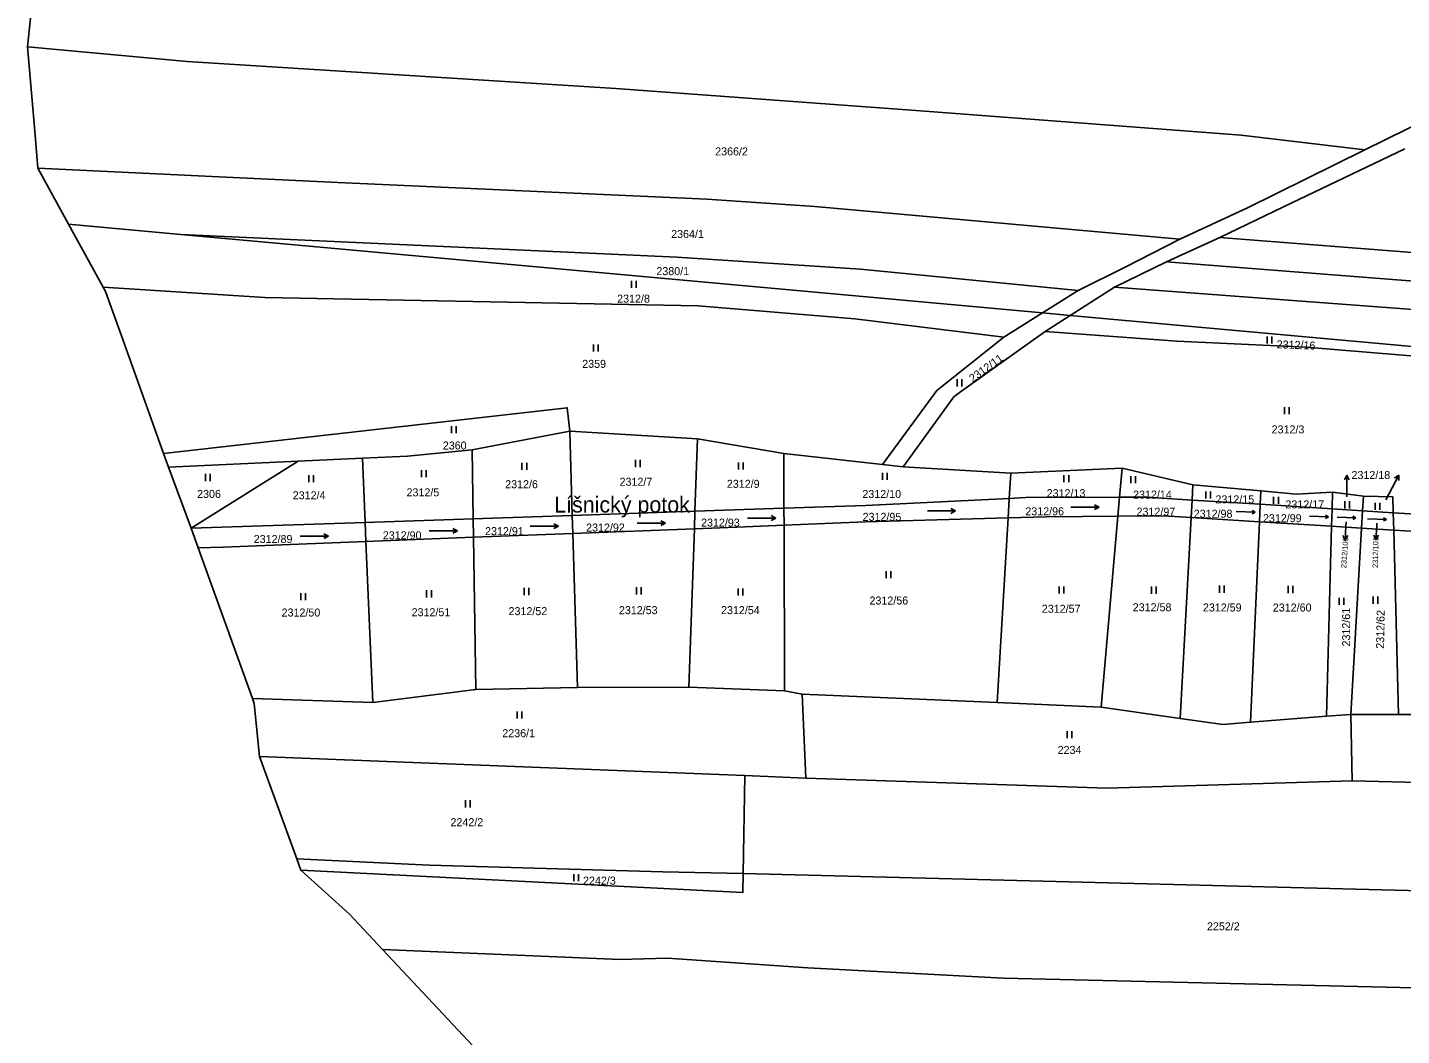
# Model space of a CAD drawing. Extents: x -776734 to -748832, y -1118122 to -976986.
# Drawn here: x -754505.9 to -754214.1, y -1116083.5 to -1115869.4 of the extents above; entities that cross this region are included whole.
import ezdxf

# ---------------------------------------------------------------- set-up
doc = ezdxf.new("R2010")
doc.units = 0
for name, color, linetype in [('KM_Hranice obce', 7, 'Continuous'), ('KM_Hranice parcel', 7, 'Continuous'), ('KM_Parcelní čísla', 7, 'Continuous'), ('KM_Pop  PČ popisy', 7, 'Continuous'), ('KM_Značky kultur', 7, 'Continuous')]:
    doc.layers.add(name, color=color, linetype=linetype)

msp = doc.modelspace()

# ---------------------------------------------------------------- linework, layer by layer
at = {"layer": 'KM_Hranice obce'}
for p, q in [((-754497.23, -1115911.22), (-754489.87, -1115924.53)), ((-754485.69, -1115935.7), (-754479.31, -1115953.55)), ((-754479.31, -1115953.55), (-754477.03, -1115959.92)), ((-754477.03, -1115959.92), (-754475.96, -1115962.78)), ((-754475.96, -1115962.78), (-754471.18, -1115975.77)), ((-754471.18, -1115975.77), (-754469.69, -1115979.94)), ((-754469.69, -1115979.94), (-754458.16, -1116011.92)), ((-754448.74, -1116045.99), (-754447.89, -1116048.35)), ((-754430.54, -1116065.2), (-754411.26, -1116085.76))]:
    msp.add_line(p, q, dxfattribs=at)
for points in [[(-754501.84, -1115833.91), (-754503.4, -1115849.07), (-754505.93, -1115873.56)], [(-754505.93, -1115873.56), (-754504.39, -1115891.4), (-754503.71, -1115899.27)], [(-754503.71, -1115899.27), (-754500.14, -1115905.85), (-754497.23, -1115911.22)], [(-754489.87, -1115924.53), (-754489.33, -1115925.51), (-754485.69, -1115935.7)], [(-754458.16, -1116011.92), (-754457.78, -1116012.97), (-754456.67, -1116024.21)], [(-754456.67, -1116024.21), (-754452.53, -1116035.47), (-754448.74, -1116045.99)], [(-754447.89, -1116048.35), (-754437.53, -1116057.74), (-754430.54, -1116065.2)]]:
    msp.add_lwpolyline(points, dxfattribs=at)
at = {"layer": 'KM_Hranice parcel'}
for p, q in [((-754473.32, -1115913.39), (-754497.23, -1115911.22)), ((-754290.29, -1115930.02), (-754473.32, -1115913.39)), ((-754252.67, -1115914.01), (-754263.97, -1115919.17)), ((-754263.97, -1115919.17), (-754275.03, -1115924.54)), ((-754284.42, -1115930.55), (-754275.03, -1115924.54)), ((-754290.29, -1115930.02), (-754282.71, -1115925.3)), ((-754298.53, -1115935.15), (-754290.29, -1115930.02)), ((-754284.42, -1115930.55), (-754290.29, -1115930.02)), ((-754289.78, -1115933.99), (-754284.42, -1115930.55)), ((-754411.5, -1115959.14), (-754390.73, -1115955.14)), ((-754390.2, -1115973.03), (-754390.73, -1115955.14)), ((-754363.59, -1115956.75), (-754390.73, -1115955.14)), ((-754411.26, -1115973.74), (-754411.5, -1115959.14)), ((-754364.14, -1115972.15), (-754363.59, -1115956.75)), ((-754345.28, -1115959.88), (-754363.59, -1115956.75)), ((-754475.96, -1115962.78), (-754448.42, -1115961.52)), ((-754471.18, -1115975.77), (-754448.42, -1115961.52)), ((-754448.42, -1115961.52), (-754434.78, -1115960.89)), ((-754434.21, -1115974.52), (-754434.78, -1115960.89)), ((-754345.24, -1115971.51), (-754345.28, -1115959.88)), ((-754324.33, -1115962.24), (-754345.28, -1115959.88)), ((-754319.91, -1115962.73), (-754324.33, -1115962.24)), ((-754319.91, -1115962.73), (-754297.07, -1115964.03)), ((-754297.39, -1115969.41), (-754297.07, -1115964.03)), ((-754297.07, -1115964.03), (-754273.41, -1115963.03)), ((-754273.95, -1115969.19), (-754273.41, -1115963.03)), ((-754273.41, -1115963.03), (-754258.36, -1115966.54)), ((-754258.54, -1115969.77), (-754258.36, -1115966.54)), ((-754258.36, -1115966.54), (-754243.96, -1115967.81)), ((-754244.09, -1115970.68), (-754243.96, -1115967.81)), ((-754228.81, -1115971.65), (-754228.71, -1115968.1)), ((-754228.71, -1115968.1), (-754222.15, -1115968.97)), ((-754297.63, -1115973.54), (-754297.39, -1115969.41)), ((-754274.3, -1115973.21), (-754273.95, -1115969.19)), ((-754258.74, -1115973.5), (-754258.54, -1115969.77)), ((-754258.54, -1115969.77), (-754244.09, -1115970.68)), ((-754244.25, -1115974.39), (-754244.09, -1115970.68)), ((-754244.09, -1115970.68), (-754228.81, -1115971.65)), ((-754222.33, -1115972.06), (-754222.15, -1115968.97)), ((-754434.21, -1115974.52), (-754411.26, -1115973.74)), ((-754411.26, -1115973.74), (-754390.2, -1115973.03)), ((-754411.2, -1115977.69), (-754411.26, -1115973.74)), ((-754390.2, -1115973.03), (-754364.14, -1115972.15)), ((-754390.09, -1115976.87), (-754390.2, -1115973.03)), ((-754364.27, -1115975.87), (-754364.14, -1115972.15)), ((-754364.14, -1115972.15), (-754345.24, -1115971.51)), ((-754345.23, -1115975.1), (-754345.24, -1115971.51)), ((-754299.96, -1116012.78), (-754297.63, -1115973.54)), ((-754277.86, -1116013.74), (-754274.3, -1115973.21)), ((-754261.09, -1116016.14), (-754258.74, -1115973.5)), ((-754244.25, -1115974.39), (-754258.74, -1115973.5)), ((-754228.91, -1115975.33), (-754228.81, -1115971.65)), ((-754228.81, -1115971.65), (-754222.33, -1115972.06)), ((-754222.54, -1115975.72), (-754222.33, -1115972.06)), ((-754222.33, -1115972.06), (-754215.82, -1115972.47)), ((-754215.71, -1115976.14), (-754215.82, -1115972.47)), ((-754215.82, -1115972.47), (-754198.63, -1115973.56)), ((-754471.18, -1115975.77), (-754434.21, -1115974.52)), ((-754434.04, -1115978.57), (-754434.21, -1115974.52)), ((-754390.09, -1115976.87), (-754411.2, -1115977.69)), ((-754364.27, -1115975.87), (-754390.09, -1115976.87)), ((-754389.11, -1116009.56), (-754390.09, -1115976.87)), ((-754365.46, -1116009.49), (-754364.27, -1115975.87)), ((-754345.1, -1116010.27), (-754345.23, -1115975.1)), ((-754246.13, -1116016.97), (-754244.25, -1115974.39)), ((-754228.91, -1115975.33), (-754244.25, -1115974.39)), ((-754230.01, -1116015.7), (-754228.91, -1115975.33)), ((-754222.54, -1115975.72), (-754228.91, -1115975.33)), ((-754224.79, -1116015.29), (-754222.54, -1115975.72)), ((-754215.71, -1115976.14), (-754222.54, -1115975.72)), ((-754214.68, -1116015.29), (-754215.71, -1115976.14)), ((-754198.91, -1115977.17), (-754215.71, -1115976.14)), ((-754411.2, -1115977.69), (-754434.04, -1115978.57)), ((-754432.59, -1116012.74), (-754434.04, -1115978.57)), ((-754410.69, -1116010.01), (-754411.2, -1115977.69)), ((-754432.59, -1116012.74), (-754458.16, -1116011.92)), ((-754410.69, -1116010.01), (-754432.59, -1116012.74)), ((-754389.11, -1116009.56), (-754410.69, -1116010.01)), ((-754365.46, -1116009.49), (-754389.11, -1116009.56)), ((-754345.1, -1116010.27), (-754365.46, -1116009.49)), ((-754341.39, -1116010.98), (-754345.1, -1116010.27)), ((-754299.96, -1116012.78), (-754341.39, -1116010.98)), ((-754341.39, -1116010.98), (-754340.56, -1116028.85)), ((-754277.86, -1116013.74), (-754299.96, -1116012.78)), ((-754261.09, -1116016.14), (-754277.86, -1116013.74)), ((-754230.01, -1116015.7), (-754246.13, -1116016.97)), ((-754224.79, -1116015.29), (-754230.01, -1116015.7)), ((-754224.51, -1116029.41), (-754224.79, -1116015.29)), ((-754214.68, -1116015.29), (-754224.79, -1116015.29)), ((-754201.78, -1116015.29), (-754214.68, -1116015.29)), ((-754353.54, -1116028.25), (-754456.67, -1116024.21)), ((-754353.92, -1116049.07), (-754353.54, -1116028.25)), ((-754353.54, -1116028.25), (-754340.56, -1116028.85)), ((-754430.54, -1116065.2), (-754380.01, -1116067.32)), ((-754380.01, -1116067.32), (-754369.97, -1116067.08))]:
    msp.add_line(p, q, dxfattribs=at)
for points in [[(-754221.88, -1115895.37), (-754203.58, -1115886.39), (-754187.62, -1115878.16), (-754165.58, -1115861.19)], [(-754221.88, -1115895.37), (-754248.15, -1115892.27), (-754316.27, -1115887.11), (-754380.93, -1115882.38), (-754472, -1115876.62), (-754505.93, -1115873.56)], [(-754261.15, -1115914.38), (-754246.75, -1115907.69), (-754221.88, -1115895.37)], [(-754213.34, -1115895.19), (-754239.16, -1115907.5), (-754252.67, -1115914.01)], [(-754261.15, -1115914.38), (-754338.69, -1115907.43), (-754361.6, -1115905.87), (-754439.97, -1115902.31), (-754503.71, -1115899.27)], [(-754473.32, -1115913.39), (-754367.96, -1115918.21), (-754328.97, -1115920.71), (-754282.71, -1115925.3)], [(-754282.71, -1115925.3), (-754272.73, -1115920.29), (-754261.15, -1115914.38)], [(-753634.31, -1115953.88), (-753782.57, -1115942.57), (-753889.17, -1115936.67), (-754003.5, -1115930.04), (-754113.87, -1115922.18), (-754186.37, -1115919.15), (-754252.67, -1115914.01)], [(-754263.97, -1115919.17), (-754191.45, -1115924.86), (-754121.71, -1115927.28), (-754050.03, -1115932.73), (-753953.82, -1115938.65), (-753852.54, -1115944.45), (-753744.49, -1115950.38), (-753671.97, -1115955.09), (-753644.38, -1115957.57)], [(-754489.87, -1115924.53), (-754455.54, -1115926.76), (-754363.43, -1115928.56), (-754330.2, -1115931.3), (-754298.53, -1115935.15)], [(-754275.03, -1115924.54), (-754188.86, -1115931.02), (-754119.84, -1115932.35), (-754015.78, -1115939.84), (-753919.33, -1115945.89), (-753841.13, -1115950.48), (-753786.6, -1115952.19), (-753712.47, -1115956.3), (-753652.17, -1115960.57)], [(-754187.17, -1115941.21), (-754188.33, -1115939.28), (-754284.42, -1115930.55)], [(-754298.53, -1115935.15), (-754312.76, -1115946.5), (-754324.33, -1115962.24)], [(-754289.78, -1115933.99), (-754307.73, -1115946.76), (-754309.15, -1115947.84), (-754319.91, -1115962.73)], [(-754187.17, -1115941.21), (-754234.35, -1115937.28), (-754261.78, -1115936.04), (-754289.78, -1115933.99)], [(-754390.73, -1115955.14), (-754391.28, -1115950.16), (-754477.03, -1115959.92)], [(-754434.78, -1115960.89), (-754425.23, -1115960.45), (-754411.5, -1115959.14)], [(-754243.96, -1115967.81), (-754236.47, -1115968.55), (-754228.71, -1115968.1)], [(-754345.24, -1115971.51), (-754327.91, -1115970.92), (-754297.39, -1115969.41)], [(-754297.39, -1115969.41), (-754293.93, -1115969.24), (-754273.95, -1115969.19)], [(-754273.95, -1115969.19), (-754268.06, -1115969.17), (-754258.54, -1115969.77)], [(-754222.15, -1115968.97), (-754215.92, -1115969.1), (-754215.82, -1115972.47)], [(-754297.63, -1115973.54), (-754327.94, -1115974.38), (-754345.23, -1115975.1)], [(-754274.3, -1115973.21), (-754289.44, -1115973.31), (-754297.63, -1115973.54)], [(-754258.74, -1115973.5), (-754264.66, -1115973.14), (-754274.3, -1115973.21)], [(-754345.23, -1115975.1), (-754353.47, -1115975.45), (-754364.27, -1115975.87)], [(-754434.04, -1115978.57), (-754464.39, -1115979.75), (-754469.69, -1115979.94)], [(-754246.13, -1116016.97), (-754252.03, -1116017.43), (-754261.09, -1116016.14)], [(-754340.56, -1116028.85), (-754276.57, -1116030.98), (-754224.51, -1116029.41)], [(-754224.51, -1116029.41), (-754105.82, -1116032.35), (-753985.44, -1116033.05)], [(-754448.74, -1116045.99), (-754420.51, -1116047.3), (-754370.95, -1116048.7), (-754353.92, -1116049.07)], [(-754447.89, -1116048.35), (-754354, -1116053.15), (-754353.92, -1116049.07)], [(-754103.29, -1116054.43), (-754201.58, -1116052.95), (-754353.92, -1116049.07)], [(-754369.97, -1116067.08), (-754340.19, -1116069.15), (-754298.57, -1116071.31), (-754187.21, -1116073.95), (-754105.4, -1116075.45)]]:
    msp.add_lwpolyline(points, dxfattribs=at)
at = {"layer": 'KM_Pop  PČ popisy'}
for p, q in [((-754225.68, -1115964.459), (-754226.181, -1115965.46)), ((-754225.68, -1115967.46), (-754225.68, -1115964.459)), ((-754225.68, -1115964.459), (-754225.179, -1115965.46)), ((-754216.02, -1115967.15), (-754214.611, -1115964.5)), ((-754214.611, -1115964.5), (-754215.523, -1115965.149)), ((-754214.611, -1115964.5), (-754214.639, -1115965.62)), ((-754225.68, -1115969.12), (-754225.68, -1115967.46)), ((-754217.37, -1115969.72), (-754216.02, -1115967.15)), ((-754225.89, -1115975.3), (-754226.047, -1115978.297)), ((-754225.84, -1115974.41), (-754225.89, -1115975.3)), ((-754219.33, -1115975.24), (-754219.487, -1115978.237)), ((-754219.3, -1115974.68), (-754219.33, -1115975.24)), ((-754226.047, -1115978.297), (-754226.495, -1115977.271)), ((-754226.047, -1115978.297), (-754225.495, -1115977.323)), ((-754219.487, -1115978.237), (-754219.935, -1115977.211)), ((-754219.487, -1115978.237), (-754218.935, -1115977.263))]:
    msp.add_line(p, q, dxfattribs=at)
at = {"layer": 'KM_Značky kultur'}
for p, q in [((-754377.601, -1115924.74), (-754377.601, -1115923.24)), ((-754376.6, -1115924.74), (-754376.6, -1115923.24)), ((-754242.601, -1115936.56), (-754242.601, -1115935.06)), ((-754241.6, -1115936.56), (-754241.6, -1115935.06)), ((-754385.701, -1115938.22), (-754385.701, -1115936.72)), ((-754384.7, -1115938.22), (-754384.7, -1115936.72)), ((-754308.441, -1115945.63), (-754308.441, -1115944.13)), ((-754307.44, -1115945.63), (-754307.44, -1115944.13)), ((-754238.941, -1115951.55), (-754238.941, -1115950.05)), ((-754237.94, -1115951.55), (-754237.94, -1115950.05)), ((-754415.841, -1115955.59), (-754415.841, -1115954.09)), ((-754414.84, -1115955.59), (-754414.84, -1115954.09)), ((-754400.891, -1115963.36), (-754400.891, -1115961.86)), ((-754399.89, -1115963.36), (-754399.89, -1115961.86)), ((-754376.801, -1115962.76), (-754376.801, -1115961.26)), ((-754375.8, -1115962.76), (-754375.8, -1115961.26)), ((-754354.871, -1115963.28), (-754354.871, -1115961.78)), ((-754353.87, -1115963.28), (-754353.87, -1115961.78)), ((-754468.121, -1115965.74), (-754468.121, -1115964.24)), ((-754467.12, -1115965.74), (-754467.12, -1115964.24)), ((-754446.161, -1115966.01), (-754446.161, -1115964.51)), ((-754445.16, -1115966.01), (-754445.16, -1115964.51)), ((-754422.241, -1115964.94), (-754422.241, -1115963.44)), ((-754421.24, -1115964.94), (-754421.24, -1115963.44)), ((-754324.341, -1115965.46), (-754324.341, -1115963.96)), ((-754323.34, -1115965.46), (-754323.34, -1115963.96)), ((-754285.761, -1115965.97), (-754285.761, -1115964.47)), ((-754284.76, -1115965.97), (-754284.76, -1115964.47)), ((-754271.591, -1115966.17), (-754271.591, -1115964.67)), ((-754270.59, -1115966.17), (-754270.59, -1115964.67)), ((-754255.621, -1115969.45), (-754255.621, -1115967.95)), ((-754254.62, -1115969.45), (-754254.62, -1115967.95)), ((-754284.313, -1115971.309), (-754278.313, -1115971.309)), ((-754278.313, -1115971.309), (-754279.29, -1115970.807)), ((-754278.313, -1115971.309), (-754279.29, -1115971.81)), ((-754241.221, -1115970.57), (-754241.221, -1115969.07)), ((-754240.22, -1115970.57), (-754240.22, -1115969.07)), ((-754226.101, -1115971.54), (-754226.101, -1115970.04)), ((-754225.1, -1115971.54), (-754225.1, -1115970.04)), ((-754219.641, -1115971.86), (-754219.641, -1115970.36)), ((-754218.64, -1115971.86), (-754218.64, -1115970.36)), ((-754370.413, -1115974.689), (-754371.39, -1115974.187)), ((-754352.983, -1115973.589), (-754346.983, -1115973.589)), ((-754346.983, -1115973.589), (-754347.96, -1115973.087)), ((-754346.983, -1115973.589), (-754347.96, -1115974.09)), ((-754314.783, -1115972.099), (-754308.783, -1115972.099)), ((-754308.783, -1115972.099), (-754309.76, -1115971.597)), ((-754308.783, -1115972.099), (-754309.76, -1115972.6)), ((-754249.147, -1115972.226), (-754245.13, -1115972.366)), ((-754245.13, -1115972.366), (-754245.796, -1115972.679)), ((-754245.13, -1115972.366), (-754245.773, -1115972.008)), ((-754233.587, -1115973.216), (-754229.57, -1115973.356)), ((-754229.57, -1115973.356), (-754230.236, -1115973.669)), ((-754229.57, -1115973.356), (-754230.213, -1115972.998)), ((-754227.757, -1115973.426), (-754223.74, -1115973.566)), ((-754223.74, -1115973.566), (-754224.406, -1115973.879)), ((-754223.74, -1115973.566), (-754224.383, -1115973.208)), ((-754221.257, -1115973.766), (-754217.24, -1115973.906)), ((-754217.24, -1115973.906), (-754217.906, -1115974.219)), ((-754217.24, -1115973.906), (-754217.883, -1115973.548)), ((-754442.013, -1115977.429), (-754442.99, -1115976.927)), ((-754420.593, -1115976.339), (-754414.593, -1115976.339)), ((-754414.593, -1115976.339), (-754415.57, -1115975.837)), ((-754414.593, -1115976.339), (-754415.57, -1115976.84)), ((-754399.133, -1115975.319), (-754393.133, -1115975.319)), ((-754393.133, -1115975.319), (-754394.11, -1115974.817)), ((-754393.133, -1115975.319), (-754394.11, -1115975.82)), ((-754376.413, -1115974.689), (-754370.413, -1115974.689)), ((-754370.413, -1115974.689), (-754371.39, -1115975.19)), ((-754448.013, -1115977.429), (-754442.013, -1115977.429)), ((-754442.013, -1115977.429), (-754442.99, -1115977.93)), ((-754323.541, -1115986.36), (-754323.541, -1115984.86)), ((-754322.54, -1115986.36), (-754322.54, -1115984.86)), ((-754400.441, -1115989.94), (-754400.441, -1115988.44)), ((-754399.44, -1115989.94), (-754399.44, -1115988.44)), ((-754376.541, -1115989.81), (-754376.541, -1115988.31)), ((-754375.54, -1115989.81), (-754375.54, -1115988.31)), ((-754354.961, -1115990.08), (-754354.961, -1115988.58)), ((-754353.96, -1115990.08), (-754353.96, -1115988.58)), ((-754286.811, -1115989.62), (-754286.811, -1115988.12)), ((-754285.81, -1115989.62), (-754285.81, -1115988.12)), ((-754267.171, -1115989.66), (-754267.171, -1115988.16)), ((-754266.17, -1115989.66), (-754266.17, -1115988.16)), ((-754252.751, -1115989.45), (-754252.751, -1115987.95)), ((-754251.75, -1115989.45), (-754251.75, -1115987.95)), ((-754238.111, -1115989.52), (-754238.111, -1115988.02)), ((-754237.11, -1115989.52), (-754237.11, -1115988.02)), ((-754447.891, -1115991.05), (-754447.891, -1115989.55)), ((-754446.89, -1115991.05), (-754446.89, -1115989.55)), ((-754421.141, -1115990.44), (-754421.141, -1115988.94)), ((-754420.14, -1115990.44), (-754420.14, -1115988.94)), ((-754227.281, -1115992.04), (-754227.281, -1115990.54)), ((-754226.28, -1115992.04), (-754226.28, -1115990.54)), ((-754220.061, -1115991.78), (-754220.061, -1115990.28)), ((-754219.06, -1115991.78), (-754219.06, -1115990.28)), ((-754401.941, -1116016.17), (-754401.941, -1116014.67)), ((-754400.94, -1116016.17), (-754400.94, -1116014.67)), ((-754285.071, -1116020.37), (-754285.071, -1116018.87)), ((-754284.07, -1116020.37), (-754284.07, -1116018.87)), ((-754412.911, -1116035.04), (-754412.911, -1116033.54)), ((-754411.91, -1116035.04), (-754411.91, -1116033.54)), ((-754389.881, -1116050.71), (-754389.881, -1116049.21)), ((-754388.88, -1116050.71), (-754388.88, -1116049.21))]:
    msp.add_line(p, q, dxfattribs=at)

# ---------------------------------------------------------------- texts
at = {"layer": 'KM_Parcelní čísla'}
for s, p in [('2366/2', (-754359.85, -1115896.58)), ('2364/1', (-754369.21, -1115914.13)), ('2380/1', (-754372.34, -1115922.01)), ('2312/8', (-754380.67, -1115927.85)), ('2359', (-754388.09, -1115941.7)), ('2312/3', (-754241.65, -1115955.62)), ('2360', (-754417.71, -1115959.04)), ('2312/6', (-754404.46, -1115967.26)), ('2312/7', (-754380.16, -1115966.74)), ('2312/9', (-754357.37, -1115967.18)), ('2312/18', (-754224.68, -1115965.31)), ('2306', (-754469.9, -1115969.32)), ('2312/4', (-754449.58, -1115969.61)), ('2312/5', (-754425.41, -1115968.99)), ('2312/10', (-754328.58, -1115969.34)), ('2312/13', (-754289.43, -1115969.17)), ('2312/14', (-754271.08, -1115969.46)), ('2312/96', (-754293.97, -1115973.02)), ('2312/97', (-754270.34, -1115973.1)), ('2312/15', (-754253.58, -1115970.48)), ('2312/17', (-754238.72, -1115971.55)), ('2312/93', (-754362.85, -1115975.41)), ('2312/95', (-754328.53, -1115974.19)), ('2312/98', (-754258.19, -1115973.53)), ('2312/99', (-754243.49, -1115974.48)), ('2312/89', (-754457.87, -1115978.9)), ('2312/90', (-754430.45, -1115978.11)), ('2312/91', (-754408.73, -1115977.23)), ('2312/92', (-754387.27, -1115976.46)), ('2312/56', (-754327.07, -1115991.96)), ('2312/58', (-754271.15, -1115993.39)), ('2312/59', (-754256.25, -1115993.44)), ('2312/60', (-754241.39, -1115993.45)), ('2312/50', (-754451.95, -1115994.51)), ('2312/51', (-754424.33, -1115994.45)), ('2312/52', (-754403.74, -1115994.22)), ('2312/53', (-754380.3, -1115994.01)), ('2312/54', (-754358.61, -1115994)), ('2312/57', (-754290.46, -1115993.71)), ('2236/1', (-754405.07, -1116020.14)), ('2234', (-754287.11, -1116023.69)), ('2242/2', (-754416.07, -1116039.04)), ('2242/3', (-754387.92, -1116051.44)), ('2252/2', (-754255.39, -1116061.15))]:
    msp.add_text(s, height=1.7, dxfattribs=at).set_placement(p)
for s, height, rotation, p in [('2312/16', 1.7, 358, (-754240.599, -1115937.539)), ('2312/11', 1.7, 36, (-754305.14, -1115944.847)), ('2312/100', 1.139, 86, (-754225.807, -1115984.295)), ('2312/101', 1.139, 89, (-754219.081, -1115984.204)), ('2312/61', 1.7, 90, (-754224.97, -1116000.88)), ('2312/62', 1.7, 89, (-754217.77, -1116001.364))]:
    msp.add_text(s, height=height, rotation=rotation, dxfattribs=at).set_placement(p)
at = {"layer": 'KM_Pop  PČ popisy'}
msp.add_text('Líšnický potok', height=3.399996, dxfattribs=at).set_placement((-754394.038, -1115972.43))

doc.saveas('drawing.dxf')
